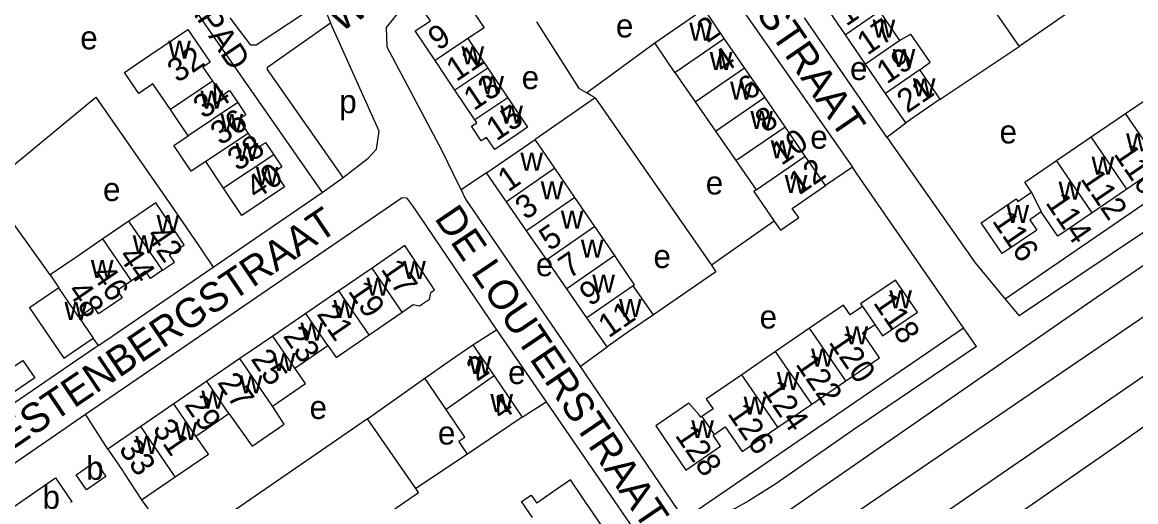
# Model space of a CAD drawing. Extents: x 157569 to 159501, y 382907 to 384670.
# Drawn here: x 158061.3 to 158251.5, y 383379.4 to 383461.2 of the extents above; entities that cross this region are included whole.
import ezdxf

# ---------------------------------------------------------------- set-up
doc = ezdxf.new("R2010")
doc.units = 0
for name, color, linetype in [('BLT_Basislijn', 7, 'Continuous'), ('BLT_Bebouwing', 7, 'Continuous'), ('BLT_Centroide', 7, 'Continuous'), ('BLT_Huisnummer', 7, 'Continuous'), ('BLT_Huisnummer_ tussenligend', 7, 'Continuous'), ('BLT_Onderverdeling_panden', 7, 'Continuous'), ('BLT_Straatnaam', 7, 'Continuous'), ('BLT_Straatnaam_verkleind', 7, 'Continuous')]:
    doc.layers.add(name, color=color, linetype=linetype)

msp = doc.modelspace()

# ---------------------------------------------------------------- linework, layer by layer
at = {"layer": 'BLT_Basislijn'}
for p, q in [((158182.25, 383466.37), (158203.13, 383436.46)), ((158244.02, 383465.72), (158231.59, 383457.07)), ((158089.52, 383465.27), (158112.57, 383432.19)), ((158112.52, 383464.71), (158113.98, 383461.11)), ((158208.98, 383441.63), (158194.95, 383462)), ((158157.71, 383449.17), (158169.37, 383457.74)), ((158218.08, 383448.1), (158231.59, 383457.07)), ((158055.36, 383433.12), (158073.88, 383448.42)), ((158159.15, 383448.33), (158148.95, 383441.19)), ((158159.15, 383448.33), (158179.02, 383419.74)), ((158208.98, 383441.63), (158212.21, 383444.08)), ((158272.26, 383443.46), (158229.21, 383413.95)), ((158140.6, 383435.51), (158136.28, 383432.63)), ((158203.13, 383436.46), (158198.51, 383433.34)), ((158066.1, 383418.08), (158055.36, 383433.12)), ((158112.57, 383432.19), (158116.12, 383434.7)), ((158093.92, 383419.44), (158112.57, 383432.19)), ((158189.76, 383427.28), (158179.02, 383419.74)), ((158224.06, 383420.18), (158229.21, 383413.95)), ((158074.36, 383406.06), (158093.92, 383419.44)), ((158229.21, 383413.95), (158231.56, 383411.11)), ((158138.3, 383406.13), (158142.32, 383408.69)), ((158142.32, 383408.69), (158150.79, 383396.4)), ((158074.36, 383406.06), (158073.44, 383407.32)), ((158156.64, 383402.45), (158161.21, 383405.81)), ((158120.31, 383393.53), (158130.08, 383400.45)), ((158146.69, 383393.83), (158150.79, 383396.4)), ((158050, 383379.11), (158072.13, 383394.33)), ((158075.96, 383388.34), (158072.13, 383394.33)), ((158128.55, 383381.6), (158120.31, 383393.53)), ((158137.38, 383387.48), (158128.55, 383381.6)), ((158113.05, 383369.93), (158129, 383380.94)), ((158129, 383380.94), (158128.55, 383381.6)), ((158081.73, 383379.69), (158087.84, 383371.18))]:
    msp.add_line(p, q, dxfattribs=at)
for points in [[(158216.7, 383478.6), (158216.97, 383478.21), (158231.59, 383457.07)], [(158141.14, 383474.02), (158140.14, 383473.32), (158125.65, 383463.03), (158123.46, 383460.32), (158123.58, 383457.03), (158133.02, 383439.34), (158135.97, 383433.26), (158136.28, 383432.63)], [(158112.52, 383464.71), (158101.31, 383457.3), (158100.37, 383457.29), (158096.82, 383461.97)], [(158116.12, 383434.7), (158103.2, 383453.15), (158103.2, 383453.56), (158113.98, 383461.11)], [(158116.12, 383434.7), (158120.4, 383438.03), (158121.85, 383439.54), (158122.3, 383442.65), (158113.98, 383461.11)], [(158157.71, 383449.17), (158156.51, 383449.87), (158149.24, 383461.32)], [(158073.88, 383448.42), (158086.63, 383430.14), (158091.48, 383423.03), (158093.92, 383419.44)], [(158159.15, 383448.33), (158158.37, 383448.79), (158157.71, 383449.17)], [(158208.98, 383441.63), (158224.06, 383420.18)], [(158191.06, 383377.09), (158244.7, 383414.23), (158281.28, 383439.16)], [(158274.71, 383440.16), (158268.52, 383435.84), (158231.56, 383411.11)], [(158222.08, 383409.05), (158203.93, 383435.32), (158203.13, 383436.46)], [(158072.13, 383394.33), (158126.23, 383431.31), (158126.93, 383431.27), (158127.99, 383429.87), (158142.32, 383408.69)], [(158136.28, 383432.63), (158137.04, 383431.04), (158156.64, 383402.45)], [(158179.02, 383419.74), (158179.79, 383418.63), (158169.11, 383411.29)], [(158094.46, 383303.58), (158123.76, 383323.12), (158150.88, 383341.57), (158262.9, 383417.82)], [(158100.7, 383295.99), (158125.39, 383313.08), (158140.85, 383323.93), (158268.87, 383411.85)], [(158174.32, 383376.41), (158222.08, 383409.05)], [(158224.27, 383405.88), (158222.08, 383409.05)], [(158074.36, 383406.06), (158073.84, 383405.71), (158053.22, 383391.62)], [(158224.27, 383405.88), (158203.54, 383391.81), (158190.05, 383382.43), (158185.42, 383379.53)], [(158156.64, 383402.45), (158174.32, 383376.41)], [(158131.9, 383308.9), (158138.33, 383313.42), (158187.3, 383347.02), (158228.07, 383374.98), (158248.84, 383389.35), (158261.15, 383398.07)], [(158150.79, 383396.4), (158167.67, 383371.92)], [(158120.31, 383393.53), (158088.11, 383371.36), (158087.84, 383371.18)], [(158185.42, 383379.53), (158182.98, 383378.15), (158179.85, 383376.32), (158175.81, 383374.22)]]:
    msp.add_lwpolyline(points, dxfattribs=at)
at = {"layer": 'BLT_Bebouwing'}
for p, q in [((158169.37, 383457.74), (158177.77, 383463.5)), ((158181.23, 383458.47), (158177.77, 383463.5)), ((158201.9, 383459.11), (158198.47, 383464.12)), ((158211.2, 383458.12), (158207.77, 383463.13)), ((158081.19, 383454.28), (158089.63, 383459.98)), ((158137.46, 383458.45), (158140.85, 383453.4)), ((158184.69, 383453.44), (158181.23, 383458.47)), ((158205.34, 383454.1), (158201.9, 383459.11)), ((158172.77, 383452.65), (158169.37, 383457.74)), ((158135.24, 383449.63), (158131.85, 383454.68)), ((158208.77, 383449.09), (158205.34, 383454.1)), ((158140.85, 383453.4), (158144.25, 383448.34)), ((158188.14, 383448.42), (158184.69, 383453.44)), ((158218.08, 383448.1), (158214.64, 383453.11)), ((158138.64, 383444.57), (158135.24, 383449.63)), ((158191.6, 383443.39), (158188.14, 383448.42)), ((158212.21, 383444.08), (158208.77, 383449.09)), ((158089.7, 383441.86), (158086.68, 383446.36)), ((158176.24, 383447.64), (158179.73, 383442.63)), ((158243.86, 383441.64), (158249.76, 383445.65)), ((158179.73, 383442.63), (158183.21, 383437.62)), ((158195.06, 383438.36), (158191.6, 383443.39)), ((158152.3, 383436.3), (158148.95, 383441.19)), ((158237.97, 383437.62), (158243.86, 383441.64)), ((158095.73, 383432.88), (158092.67, 383437.43)), ((158198.51, 383433.34), (158195.06, 383438.36)), ((158144.03, 383430.56), (158140.6, 383435.51)), ((158155.7, 383431.33), (158152.3, 383436.3)), ((158255.83, 383436.75), (158249.95, 383432.73)), ((158192.8, 383429.42), (158198.51, 383433.34)), ((158159.11, 383426.35), (158155.7, 383431.33)), ((158249.95, 383432.73), (158244.06, 383428.71)), ((158147.47, 383425.61), (158144.03, 383430.56)), ((158079.56, 383427.27), (158075.11, 383424.23)), ((158150.9, 383420.66), (158147.47, 383425.61)), ((158162.51, 383421.38), (158159.11, 383426.35)), ((158075.11, 383424.23), (158070.66, 383421.19)), ((158070.66, 383421.19), (158066.1, 383418.08)), ((158154.34, 383415.71), (158150.9, 383420.66)), ((158163.05, 383420.59), (158162.51, 383421.38)), ((158165.91, 383416.41), (158163.05, 383420.59)), ((158121.07, 383419.25), (158115.43, 383415.39)), ((158165.91, 383416.41), (158165.66, 383416.23)), ((158115.43, 383415.39), (158109.79, 383411.52)), ((158157.77, 383410.76), (158154.34, 383415.71)), ((158204.82, 383412.69), (158202.74, 383411.26)), ((158109.79, 383411.52), (158104.15, 383407.66)), ((158161.21, 383405.81), (158157.77, 383410.76)), ((158195.78, 383408.98), (158189.99, 383405.02)), ((158104.15, 383407.66), (158098.52, 383403.8)), ((158107.91, 383402.17), (158113.55, 383406.03)), ((158138.3, 383406.13), (158141.9, 383400.86)), ((158189.99, 383405.02), (158184.21, 383401.05)), ((158098.52, 383403.8), (158092.88, 383399.93)), ((158141.9, 383400.86), (158146.69, 383393.83)), ((158092.88, 383399.93), (158087.24, 383396.07)), ((158133.72, 383395.12), (158130.08, 383400.45)), ((158196.18, 383396.02), (158201.97, 383399.98)), ((158087.24, 383396.07), (158081.6, 383392.21)), ((158179.31, 383395.21), (158177.41, 383393.91)), ((158190.38, 383392.07), (158196.18, 383396.02)), ((158090.99, 383390.58), (158096.63, 383394.44)), ((158081.6, 383392.21), (158075.96, 383388.34)), ((158179.51, 383390.85), (158181.4, 383392.15)), ((158070.54, 383383.96), (158073.87, 383386.22)), ((158073.87, 383386.22), (158075.63, 383383.66)), ((158072.29, 383381.39), (158070.54, 383383.96)), ((158075.63, 383383.66), (158072.29, 383381.39)), ((158081.73, 383379.69), (158087.46, 383383.63))]:
    msp.add_line(p, q, dxfattribs=at)
for points in [[(158131.85, 383454.68), (158128.45, 383459.74), (158131.04, 383461.48), (158129.2, 383464.22), (158134.68, 383467.9), (158136.52, 383465.16), (158136.8, 383465.35), (158140.2, 383460.29), (158137.46, 383458.45)], [(158089.63, 383459.98), (158093.42, 383454.42), (158092.18, 383453.58), (158093.81, 383451.15)], [(158214.64, 383453.11), (158216.4, 383454.4), (158213.09, 383459.22), (158211.2, 383458.12)], [(158086.68, 383446.36), (158083.62, 383450.7), (158081.26, 383449.09), (158078.82, 383452.66), (158081.19, 383454.28)], [(158172.77, 383452.65), (158176.24, 383447.64)], [(158093.81, 383451.15), (158095.44, 383448.72), (158096.76, 383449.6), (158098.15, 383447.52)], [(158144.25, 383448.34), (158147.64, 383443.29), (158145.93, 383442.14), (158142.03, 383439.52), (158140.64, 383441.58), (158139.73, 383440.97), (158138.06, 383443.46), (158138.97, 383444.07), (158138.64, 383444.57)], [(158249.76, 383445.65), (158255.56, 383449.6), (158256.72, 383447.9)], [(158098.15, 383447.52), (158099.54, 383445.45), (158098.34, 383444.64), (158099.93, 383442.22)], [(158218.08, 383448.1), (158216.12, 383446.76), (158212.21, 383444.08)], [(158092.67, 383437.43), (158090.19, 383435.79), (158087.21, 383440.16), (158089.7, 383441.86)], [(158099.93, 383442.22), (158101.53, 383439.81), (158102.87, 383440.71), (158104.28, 383438.61)], [(158140.6, 383435.51), (158148.95, 383441.19)], [(158104.28, 383438.61), (158105.68, 383436.52), (158104.42, 383435.67), (158106.12, 383433.14), (158098.83, 383428.24), (158096.05, 383432.4), (158095.73, 383432.88)], [(158183.21, 383437.62), (158186.69, 383432.61)], [(158233.71, 383432.24), (158232.55, 383433.94), (158237.97, 383437.62)], [(158186.69, 383432.61), (158186.28, 383432.33)], [(158186.28, 383432.33), (158189.76, 383427.28)], [(158235.34, 383428.85), (158233.38, 383427.51), (158234.58, 383425.74), (158228.7, 383421.72), (158225.09, 383427.01), (158231.04, 383431.08), (158231.35, 383430.62), (158233.71, 383432.24)], [(158085.3, 383418.88), (158087.33, 383420.27), (158086.47, 383421.52), (158089.01, 383423.25), (158086.19, 383427.38), (158084.13, 383430.4), (158079.56, 383427.27)], [(158189.76, 383427.28), (158190.82, 383425.73), (158193.95, 383427.89), (158192.8, 383429.42)], [(158244.06, 383428.71), (158238.17, 383424.69), (158235.34, 383428.85)], [(158126.2, 383411.75), (158128.09, 383413.03), (158129.18, 383412.81), (158130.88, 383413.97), (158131.09, 383415.08), (158131.72, 383415.52), (158126.7, 383423.11), (158121.07, 383419.25)], [(158066.1, 383418.08), (158067.6, 383415.88)], [(158085.3, 383418.88), (158083.27, 383417.5), (158082.41, 383418.76), (158079.98, 383417.09)], [(158079.98, 383417.09), (158077.55, 383415.43), (158078.4, 383414.18), (158076.39, 383412.81)], [(158169.11, 383411.29), (158165.66, 383416.23)], [(158206.92, 383409.61), (158208.24, 383407.69), (158214.19, 383411.75), (158210.45, 383417.21), (158204.51, 383413.14), (158204.82, 383412.69)], [(158067.6, 383415.88), (158062.59, 383412.47), (158068.43, 383403.9), (158073.44, 383407.32)], [(158076.39, 383412.81), (158074.37, 383411.43), (158073.56, 383412.62), (158071.02, 383410.88)], [(158202.74, 383411.26), (158201.58, 383412.95), (158195.78, 383408.98)], [(158071.02, 383410.88), (158073.44, 383407.32)], [(158120.56, 383407.87), (158126.2, 383411.75)], [(158169.11, 383411.29), (158164.95, 383408.41), (158161.21, 383405.81)], [(158204.83, 383408.18), (158206.92, 383409.61)], [(158055.93, 383408.07), (158056.96, 383406.56), (158059.81, 383402.37), (158061.47, 383403.49), (158063.48, 383400.53), (158058.3, 383397), (158056.5, 383399.64)], [(158113.55, 383406.03), (158114.93, 383404.01), (158120.56, 383407.87)], [(158201.97, 383399.98), (158207.75, 383403.92), (158204.83, 383408.18)], [(158130.08, 383400.45), (158134.47, 383403.52), (158138.3, 383406.13)], [(158104.08, 383395.66), (158109.73, 383399.54), (158107.91, 383402.17)], [(158184.21, 383401.05), (158178.15, 383396.9), (158179.31, 383395.21)], [(158096.63, 383394.44), (158100.6, 383388.87), (158106.04, 383392.61), (158104.08, 383395.66)], [(158137.38, 383387.48), (158135.88, 383389.68), (158136.94, 383390.41), (158133.72, 383395.12)], [(158177.41, 383393.91), (158177.22, 383393.78), (158176.91, 383394.23), (158175.17, 383396.2), (158169.53, 383392.33), (158174.64, 383384.74), (158180.6, 383388.84), (158179.31, 383390.72), (158179.51, 383390.85)], [(158146.69, 383393.83), (158142.83, 383391.2), (158137.38, 383387.48)], [(158181.4, 383392.15), (158184.29, 383387.92), (158190.38, 383392.07)], [(158087.46, 383383.63), (158093.13, 383387.46), (158090.99, 383390.58)], [(158075.96, 383388.34), (158078.57, 383384.53), (158078.83, 383384.14), (158081.73, 383379.69)], [(158060.33, 383372.85), (158057.53, 383376.93), (158067.02, 383383.43), (158069.81, 383379.35), (158069.6, 383379.21)], [(158154.48, 383371.02), (158160.42, 383375.09), (158156.72, 383380.48), (158154.95, 383383.08), (158152.08, 383381.12), (158149.19, 383379.13)], [(158148.48, 383376.66), (158146.61, 383379.38), (158148.25, 383380.51), (158149.19, 383379.13)]]:
    msp.add_lwpolyline(points, dxfattribs=at)
at = {"layer": 'BLT_Onderverdeling_panden'}
for p, q in [((158207.77, 383463.13), (158201.9, 383459.11)), ((158137.46, 383458.45), (158131.85, 383454.68)), ((158172.77, 383452.65), (158181.23, 383458.47)), ((158211.2, 383458.12), (158205.34, 383454.1)), ((158140.85, 383453.4), (158135.24, 383449.63)), ((158176.24, 383447.64), (158184.69, 383453.44)), ((158214.64, 383453.11), (158208.77, 383449.09)), ((158093.81, 383451.15), (158086.68, 383446.36)), ((158144.25, 383448.34), (158138.64, 383444.57)), ((158179.73, 383442.63), (158188.14, 383448.42)), ((158098.15, 383447.52), (158089.7, 383441.86)), ((158255.83, 383436.75), (158249.76, 383445.65)), ((158183.21, 383437.62), (158191.6, 383443.39)), ((158099.93, 383442.22), (158092.67, 383437.43)), ((158249.95, 383432.73), (158243.86, 383441.64)), ((158104.28, 383438.61), (158095.73, 383432.88)), ((158186.69, 383432.61), (158195.06, 383438.36)), ((158244.06, 383428.71), (158237.97, 383437.62)), ((158152.3, 383436.3), (158144.03, 383430.56)), ((158155.7, 383431.33), (158147.47, 383425.61)), ((158233.71, 383432.24), (158235.34, 383428.85)), ((158085.3, 383418.88), (158079.56, 383427.27)), ((158159.11, 383426.35), (158150.9, 383420.66)), ((158079.98, 383417.09), (158075.11, 383424.23)), ((158162.51, 383421.38), (158154.34, 383415.71)), ((158126.2, 383411.75), (158121.07, 383419.25)), ((158165.66, 383416.23), (158157.77, 383410.76)), ((158071.02, 383410.88), (158067.6, 383415.88)), ((158120.56, 383407.87), (158115.43, 383415.39)), ((158204.82, 383412.69), (158206.92, 383409.61)), ((158113.55, 383406.03), (158109.79, 383411.52)), ((158201.97, 383399.98), (158195.78, 383408.98)), ((158107.91, 383402.17), (158104.15, 383407.66)), ((158196.18, 383396.02), (158189.99, 383405.02)), ((158104.08, 383395.66), (158098.52, 383403.8)), ((158141.9, 383400.86), (158133.72, 383395.12)), ((158190.38, 383392.07), (158184.21, 383401.05)), ((158096.63, 383394.44), (158092.88, 383399.93)), ((158090.99, 383390.58), (158087.24, 383396.07)), ((158177.41, 383393.91), (158179.51, 383390.85)), ((158087.46, 383383.63), (158081.6, 383392.21))]:
    msp.add_line(p, q, dxfattribs=at)

# ---------------------------------------------------------------- texts
at = {"layer": 'BLT_Centroide'}
for s, p in [('e', (158162.72, 383458.64)), ('w', (158206.55, 383458.62)), ('e', (158071.25, 383456.6)), ('w', (158175.26, 383458.06)), ('w', (158086.27, 383455.02)), ('w', (158136.35, 383454.03)), ('w', (158178.74, 383453.06)), ('w', (158209.98, 383453.59)), ('e', (158202.7, 383451.36)), ('w', (158139.74, 383449)), ('e', (158146.63, 383449.81)), ('w', (158182.21, 383448.03)), ('w', (158213.42, 383448.59)), ('w', (158091.76, 383446.5)), ('p', (158115.48, 383445.71)), ('w', (158142.98, 383443.94)), ('w', (158095.2, 383442.47)), ('w', (158185.68, 383443.03)), ('e', (158195.91, 383439.64)), ('e', (158228.23, 383440.54)), ('w', (158189.15, 383438)), ('w', (158249.84, 383439.19)), ('w', (158097.77, 383437.56)), ('w', (158146.41, 383435.88)), ('w', (158243.95, 383435.19)), ('w', (158101.23, 383433.44)), ('e', (158178.06, 383431.82)), ('w', (158191.55, 383432.06)), ('e', (158075.14, 383430.71)), ('w', (158149.88, 383430.97)), ('w', (158238.31, 383430.95)), ('w', (158229.42, 383426.97)), ('w', (158084.28, 383425.27)), ('w', (158153.3, 383426)), ('w', (158080.2, 383421.8)), ('w', (158156.73, 383421.03)), ('e', (158169.13, 383419.27)), ('w', (158073.06, 383417.56)), ('w', (158126.39, 383417.39)), ('e', (158149.05, 383417.87)), ('w', (158158.69, 383415.06)), ('w', (158120.12, 383414.56)), ('w', (158209.41, 383412.41)), ('w', (158068.56, 383410.41)), ('w', (158114.48, 383410.72)), ('w', (158163.25, 383410.91)), ('e', (158187.26, 383408.94)), ('w', (158108.85, 383406.84)), ('w', (158201.91, 383406.22)), ('w', (158104.12, 383401.66)), ('w', (158196.05, 383402.45)), ('w', (158137.61, 383401.16)), ('w', (158098.48, 383397.88)), ('e', (158144.31, 383399.46)), ('w', (158190.2, 383398.47)), ('w', (158091.94, 383395.25)), ('w', (158141.28, 383394.66)), ('w', (158184.52, 383394.25)), ('e', (158110.4, 383393.49)), ('w', (158175.59, 383390.22)), ('w', (158087.36, 383389.89)), ('e', (158132.32, 383389.13)), ('w', (158080.66, 383387.53)), ('b', (158072.26, 383383.11)), ('b', (158064.81, 383378.16))]:
    msp.add_text(s, height=4, dxfattribs=at).set_placement(p)
at = {"layer": 'BLT_Huisnummer'}
for s, rotation, p in [('15', 34.4233, (158202.05, 383460.44)), ('2', 34.5115, (158178.32, 383457.6)), ('9', 33.8969, (158132.38, 383456.28)), ('32', 33.8602, (158087.86, 383450.78)), ('6', 34.5162, (158185.31, 383447.71)), ('21', 34.4233, (158212.47, 383445.61)), ('36', 33.8602, (158095.21, 383440.1)), ('15', 33.8928, (158142.3, 383440.84)), ('110', 304.337, (158247.62, 383438.75)), ('40', 33.8602, (158101.26, 383430.85)), ('12', 34.5094, (158193.99, 383431.6)), ('1', 34.7565, (158144.33, 383432.15)), ('116', 304.3343, (158226.86, 383427.31)), ('42', 304.3515, (158082.38, 383424.81)), ('5', 34.7494, (158151.4, 383422.07)), ('17', 304.364, (158122.46, 383419.08)), ('48', 304.348, (158068.94, 383415.36)), ('118', 304.4966, (158206.55, 383413.33)), ('21', 304.364, (158111.53, 383411.41)), ('11', 34.75, (158161.48, 383407.23)), ('25', 304.364, (158100.26, 383403.74)), ('2', 34.2977, (158138.97, 383399.79)), ('122', 304.4945, (158193.28, 383402.87)), ('29', 304.364, (158088.93, 383395.92)), ('4', 34.2952, (158143.11, 383393.11)), ('128', 304.4963, (158172.71, 383390.69)), ('33', 304.364, (158077.71, 383388.36))]:
    msp.add_text(s, height=4, rotation=rotation, dxfattribs=at).set_placement(p)
at = {"layer": 'BLT_Huisnummer_ tussenligend'}
for s, rotation, p in [('17', 34.4233, (158205.65, 383455.49)), ('11', 33.8969, (158135.48, 383451)), ('4', 34.5115, (158181.06, 383452.29)), ('19', 34.4233, (158209, 383450.57)), ('13', 33.8969, (158138.45, 383446.03)), ('34', 33.8602, (158092.29, 383444.63)), ('8', 34.5162, (158188.27, 383442.21)), ('10', 34.5162, (158190.98, 383436.66)), ('38', 33.8602, (158098.12, 383435.69)), ('112', 304.337, (158241.94, 383434.5)), ('3', 34.7565, (158147.31, 383427.37)), ('114', 304.337, (158235.98, 383430.41)), ('44', 304.3515, (158077.65, 383421.29)), ('7', 34.7494, (158154.73, 383417.34)), ('46', 304.3515, (158073.13, 383418.14)), ('19', 304.364, (158116.86, 383415.33)), ('9', 34.7494, (158158.28, 383412.62)), ('23', 304.364, (158105.77, 383407.65)), ('120', 304.4945, (158198.97, 383406.61)), ('27', 304.364, (158094.55, 383399.72)), ('124', 304.4945, (158187.57, 383398.36)), ('126', 304.4945, (158181.67, 383394.42)), ('31', 304.364, (158083.49, 383391.8))]:
    msp.add_text(s, height=4, rotation=rotation, dxfattribs=at).set_placement(p)
at = {"layer": 'BLT_Straatnaam'}
for s, height, rotation, p in [('WESTENBERGSTRAAT', 5, 33.9046, (158115.63, 383459.34)), ('KRABBESTRAAT', 4.9999, 304.4805, (158171.19, 383485.14)), ('WESTENBERGSTRAAT', 5, 34, (158054.16, 383384.45)), ('DE LOUTERSTRAAT', 5, 304.0922, (158131.61, 383427.77))]:
    msp.add_text(s, height=height, rotation=rotation, dxfattribs=at).set_placement(p)
at = {"layer": 'BLT_Straatnaam_verkleind'}
msp.add_text('GRATAMAPAD', height=4, rotation=303.9061, dxfattribs=at).set_placement((158076.3, 383483.77))

doc.saveas('drawing.dxf')
